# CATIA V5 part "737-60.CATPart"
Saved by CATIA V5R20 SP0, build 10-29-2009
Part number: 737-60
Definition: NONE
Nomenclature: 737-60
Source: Unknown
Description: 737-60
Bounding box of the stored display mesh (mm): x -60 to 46, y -59.896 to 59.896, z -60 to 42
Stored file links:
  C:\Users\Utente\Desktop\IO LAVORO\3D X SITO CF\X SITO\737\737-60.CATPart
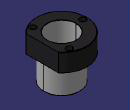
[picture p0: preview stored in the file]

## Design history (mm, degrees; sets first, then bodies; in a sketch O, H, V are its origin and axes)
Body1 "737-60" (main body)
  Solid1: solid without history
